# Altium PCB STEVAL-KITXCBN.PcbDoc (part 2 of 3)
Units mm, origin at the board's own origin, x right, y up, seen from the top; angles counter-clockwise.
Board outline 110 x 100 mm, 4 copper layers (Top Layer, GND, PWR, Bottom Layer), stack 1.53 mm thick; 227 components, 137 nets, 699 pads, 698 vias.
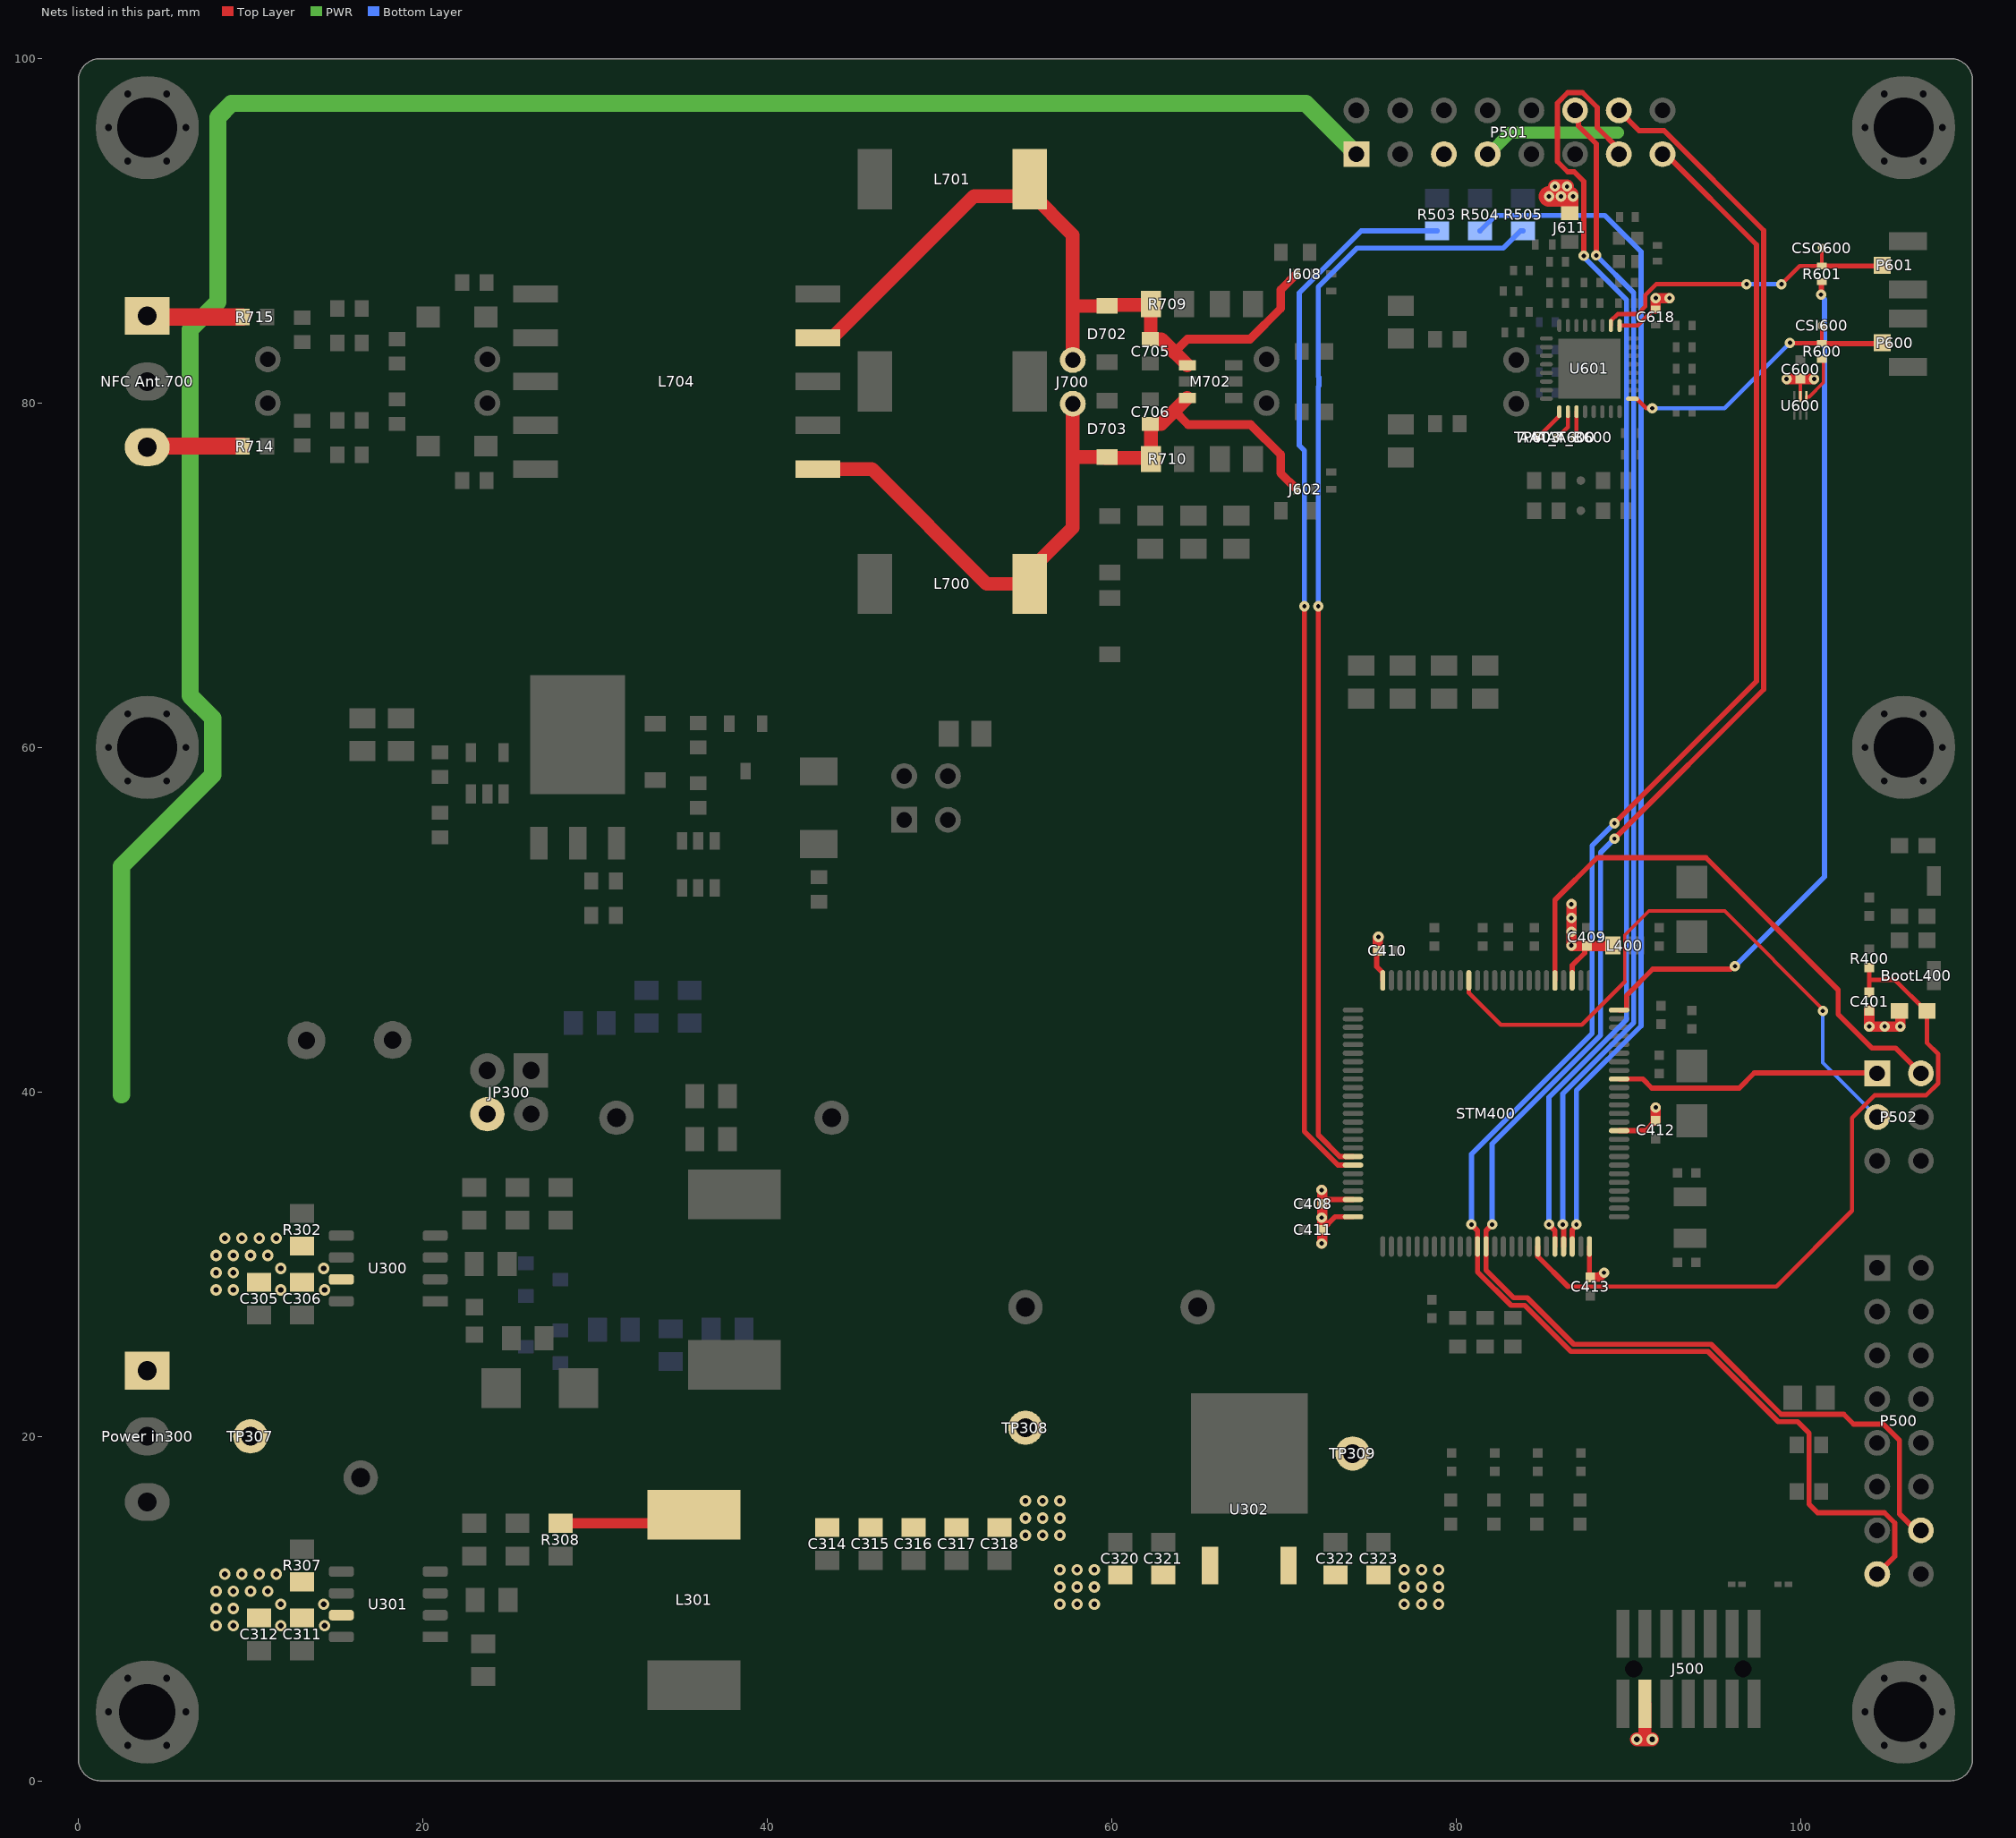
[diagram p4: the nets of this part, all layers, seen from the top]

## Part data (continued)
D700 D704 D705: library part CMP-1060-00492-1, "DIODE ZENER 20V 500MW SOD123", Forward Voltage=900mV, Manufacturer=MCC, Manufacturer Part Number=MMSZ5250B-TP, Max Operating Temperature=150°C, Max Power Dissipation=500mW, Max Reverse Current=100nA, Min Operating Temperature=-55°C, Package Quantity=1, Supplier Part Number 1=MMSZ5250B-TPMSCT-ND, Test Current=6.2mA, Tolerance=5%, Working Voltage=20V
D701: library part CMP-2000-07176-1, "Low Drop Power Schottky Rectifier, 2 A, 25 V, 2-Pin SMD (SMB), RoHS, Tape and Reel", Average Rectified Current=2A, Case/Package=SMB, Forward Voltage=530mV, Manufacturer=STMicroelectronics, Max Forward Surge Current (Ifsm)=75A, Max Operating Temperature=150°C, Max Repetitive Reverse Voltage (Vrrm)=25V, Max Reverse Current=90uA, Min Operating Temperature=-65°C, Package Quantity=1, Supplier Part Number 1=0249404
D702 D703: library part CMP-0895-00001-2, "Switching Diode, 2-Pin SOD-123, Pb-Free, Tape and Reel", Manufacturer="On Semiconductor", Supplier Part Number 1=MMSD4148T1GOSTR-ND
J400 J401 J402: library part solder_jumper_open
J500: "CONNECTOR FTSH-107-01-L-DV-K-A", Manufacturer=SAMTEC, Supplier Part Number 1=FTSH-107-01-L-DV-K-A-ND
J602 J604 J607 J608 J610: library part solder_jumper_open_0402
J603 J609 J611: library part solder_jumper_closed, "0R", Manufacturer=Multicomp, Manufacturer Part Number=MC00625W040210R, Supplier Part Number 1=1357983
J605 J606 J700 J701 J702: library part "Header 2", "Male Single Row Horizontal 2 pin"
JP300: library part JUMPER2V, "2x2 Pin Header", Package=0805, Supplier Part Number 1="2856669 & 2396301"
L300: library part CMP-0227-00732-1, "SMD-Shielded Power Inductor WE-PD, L = 56.0 µH", Case/Size Code=4747, DC Resistance (DCR)=0.11mR, Inductance="56.0 ÂµH", Inductor Application="POWER INDUCTOR", Inductor Type="GENERAL PURPOSE INDUCTOR", Manufacturer="Wurth Electronics", Manufacturer Part Number=744771156, Max Operating Temperature=125°C, Min Operating Temperature=-40°C, Rated Current-Max=2.01A, Self Resonant Frequency=7MHz, Supplier Part Number 1=732-1391-1-ND, Test Frequency=1kHz, Tolerance=20%
L301: library part CMP-0227-00726-1, "SMD-Shielded Power Inductor WE-PD, L = 33.0 µH", Case/Size Code=4747, DC Resistance (DCR)=57mR, Inductance="33.0 ÂµH", Inductor Application="POWER INDUCTOR", Inductor Type="GENERAL PURPOSE INDUCTOR", Manufacturer="Wurth Electronics", Manufacturer Part Number=744771133, Max Operating Temperature=125°C, Min Operating Temperature=-40°C, Package Height=6mm, Package Length=12mm, Package Style=SMTMeter, Rated Current-Max=2.68A, Self Resonant Frequency=10MHz, Supplier Part Number 1=732-1212-1-ND, Test Frequency=1kHz, Tolerance=20%
L400: library part BLM18AG601SN1D, "Ferrite Chip, 1 Function(s), 0.5A, 2 Pin(s)", Case Code=0603, Current Rating=500mA, DC Resistance-Max=380mR, Manufacturer=MURATA, Max Frequency=100MHz, Max Operating Temperature=125°C, Min Operating Temperature=-55°C, Supplier Part Number 1=490-1014-2-ND
L700 L701 L702: library part CMP-1396-00035-1, "SMD-Shielded Power Inductor WE-PD, L=10.0 µH", Inductance="10.0 ÂµH", Manufacturer="Wuerth Elektronik", Supplier Part Number 1=2082675
L703 L705: library part CMP-06042-016297-1, "FIXED IND 470NH 1.4A 70 MOHM SMD", Case Code (Imperial)=1206, Case Code (Metric)=3216, Current Rating=1.4A, DC Resistance (DCR)=87.5mR, Inductance=470nH, Max Operating Temperature=125°C, Min Operating Temperature=-55°C, Package Quantity=3000, Self Resonant Frequency=80MHz, Supplier Part Number 1=490-8429-1-ND, Test Frequency=1MHz, Tolerance=20%
L704: library part 42, Manufacturer=Wurth, Manufacturer PN=750371385
LD401 LD402 LD403 LD404: library part LED2, "LED Uni-Color White 7000K 2-Pin Chip 0603(1608Metric) T/R / LED COOL WHITE 0603 SMD", Case Code (Imperial)=0603, Case Code (Metric)=1608, Color=White, Correlated Color Temperature (CCT)="7000 K", Forward Current=5mA, Forward Voltage=3.15V, Manufacturer="Vishay Semiconductors", Manufacturer Part Number=VLMW1300-GS08, Max Operating Temperature=80°C, Max Power Dissipation=70mW, Min Operating Temperature=-20°C, Package Quantity=3000, Supplier Part Number 1=2251493
M700: library part "P-MOS RSR020P05TL", "Mosfet P-ch 30V 2A S-mini", Case/Package=TO-236-3, Continuous Drain Current (ID)=2A, Drain to Source Voltage (Vdss)=30V, Input Capacitance=159pF, Manufacturer=Toshiba, Max Power Dissipation=600mW, Supplier Part Number 1=SSM3J353FLFCT-ND
M701: "Trans MOSFET N-CH 30V 6A 6-Pin SOT-23 T/R", Case/Package=SOT-23-6, Continuous Drain Current (ID)=6A, Drain to Source Breakdown Voltage=30V, Drain to Source Resistance=40mR, Gate to Source Voltage (Vgs)=20V, Input Capacitance=283pF, Manufacturer=STMicroelectronics, Manufacturer Part Number=STT6N3LLH6, Max Operating Temperature=150°C, Max Power Dissipation=1.6W, Min Operating Temperature=-55°C, Package Quantity=3000, Supplier Part Number 1=07AH7134
M702: library part NDC7002N, "Transistor MOSFET Array Dual N-CH 45V 6-Pin SOT-457T Emboss T/R", Continuous Drain Current (ID)=1A, Drain to Source Voltage (Vdss)=45V, Manufacturer=Rohm, Max Operating Temperature=150°C, Max Power Dissipation=1.25W, Supplier Part Number 1=846-QS6K21FRACT-ND, Threshold Voltage=1.5V
"NFC Ant.700" "Power in300": library part HEADER3, "Screw terminal", Manufacturer="Würth Electronics", Manufacturer Part Number=691214310003, Package=TBD, Supplier Part Number 1=732-691214310003-ND
P500: "Board Connector, 16 Contact(s), 2 Row(s), Female, Straight, 0.1 inch Pitch, Solder Terminal, Black Insulator, Socket", Contact Resistance=10mR, Insulation Color=Black, Manufacturer="Würth Electronics", Manufacturer Part Number=61301621121, Max Operating Temperature=125°C, Min Operating Temperature=-65°C, Supplier Part Number 1=2356136
P501: "Board Connector, 16 Contact(s), 2 Row(s), Male, Straight, 0.1 inch Pitch, Solder Terminal", Manufacturer="Würth Electronics", Manufacturer Part Number=61301621121, Manufacturer Series=HTSW, Supplier Part Number 1=2356136
P502: "Board Connector, 6 Contact(s), 2 Row(s), Male, Straight, 0.1 inch Pitch, Solder Terminal, Black Insulator", Flammability Rating="UL94 V-0", Insulation Color=Black, Manufacturer=Samtec, Manufacturer Part Number=TSW-103-07-F-D, Supplier Part Number 1=SAM10846-ND
P600 P601: Manufacturer="Würth Electronics", Manufacturer Part Number=636101111001, Supplier Part Number 1=3843345
P700: "Header, 2-Pin, Dual row", Supplier Part Number 1=0757571121
Q300 Q301: library part CMP-1048-00779-1, "General Purpose Transistor, NPN Silicon, 3-Pin SOT-23, Pb-Free, Tape and Reel", Manufacturer="On Semiconductor", Supplier Part Number 1=5449393
R300: library part RESISTOR, "Resistor", Package=TBD, Supplier Part Number 1=812-3350, Tolerance=1%
R301 R302 R307: library part RESISTOR, "Resistor", Package=TBD, Supplier Part Number 1=812-3375, Tolerance=1%
R303: library part RESISTOR, "Res Thin Film 0805 150K Ohm 0.1% 1/8W ±25ppm/°C Molded SMD SMD Punched Carrier T/R", Case Code (Imperial)=0805, Case Code (Metric)=2012, Manufacturer=Panasonic, Manufacturer Part Number=ERA-6AEB154V, Max Operating Temperature=155°C, Max Power Dissipation=125mW, Min Operating Temperature=-55°C, Package Quantity=5000, Resistance=150kR, Resistance Tolerance=0.1%, Resistor Type="Thin Film", Supplier Part Number 1=P150KDACT-ND, Temperature Coefficient=25ppm/°C, Voltage Rating=100V
R304: library part RESISTOR, "Res Thick Film 0805 1KOhm 1% 0.125W(1/8W) 100ppm/C Epoxy Pad SMD T/R", Case Code (Imperial)=0805, Case Code (Metric)=2012, Manufacturer=Yageo, Manufacturer Part Number=RC0805FR-071KL, Max Operating Temperature=155°C, Max Power Dissipation=125mW, Min Operating Temperature=-55°C, Package Quantity=1, Resistance=1kR, Resistance Tolerance=1%, Resistor Type="Thick Film", Supplier Part Number 1=311-1.00KCRTR-ND, Temperature Coefficient=100ppm/°C, Voltage Rating=150V
R305: library part RESISTOR, "Res Thick Film 0805 33K Ohm 5% 1/8W ±200ppm/°C Molded SMD Embossed Carrier T/R", Case Code (Imperial)=0805, Case Code (Metric)=2012, Manufacturer=Panasonic, Manufacturer Part Number=ERJ-6GEYJ333V, Max Operating Temperature=155°C, Max Power Dissipation=125mW, Min Operating Temperature=-55°C, Package Quantity=5000, Resistance=33kR, Resistance Tolerance=5%, Resistor Type="Thick Film", Supplier Part Number 1=P33KATR-ND, Temperature Coefficient=200ppm/°C, Voltage Rating=150V
R306: library part RESISTOR, "Res Thick Film 0805 20K Ohm 1% 1/8W +/-100ppm/ßC Molded SMD Punched Carrier T/R", Case Code (Imperial)=0805, Case Code (Metric)=2012, Manufacturer=Panasonic, Manufacturer Part Number=ERJ-6ENF2002V, Max Operating Temperature=155°C, Max Power Dissipation=125mW, Min Operating Temperature=-55°C, Package Quantity=1, Resistance=20kR, Resistance Tolerance=1%, Resistor Type="Thick Film", Supplier Part Number 1=P20.0KCCT-ND, Temperature Coefficient=100ppm/°C, Voltage Rating=150V
R308: library part RESISTOR, "Fixed Resistor, Metal Glaze/thick Film, 0.125W, 402000ohm, 150V, 1% +/-Tol, 100ppm/Cel, Surface Mount, 0805", Manufacturer=Panasonic, Manufacturer Part Number=ERJ-6ENF4023V, Max Operating Temperature=155°C, Min Operating Temperature=-55°C, Package Height=0.6mm, Package Length=2mm, Package Shape=Rectangular, Package Style=SMTMeter, Package Width=1.25mm, Rated Power Dissipation (P)=125mW, Rated Temperature=70°C, Resistor Type="FIXED RESISTOR", Supplier Part Number 1=P402KCCT-ND, Temperature Coefficient=100ppm/°C, Tolerance=1%, Working Voltage=150V
R309: library part RESISTOR, "Fixed Resistor, Thin Film, 0.125W, 82000ohm, 150V, 0.1% +/-Tol, 25ppm/Cel, Surface Mount, 0805", Manufacturer=Yageo, Manufacturer Part Number=RT0805BRD0782KL, Max Operating Temperature=155°C, Min Operating Temperature=-55°C, Package Height=0.5mm, Package Length=2mm, Package Style=SMTMeter, Package Width=1.25mm, Rated Power Dissipation (P)=125mW, Rated Temperature=70°C, Resistor Type="FIXED RESISTOR", Supplier Part Number 1=YAG1981CT-ND, Temperature Coefficient=25ppm/°C, Tolerance=0.1%, Working Voltage=150V
R310: library part RESISTOR, "Res Thick Film 0805 820 Ohm 1% 0.125W ±100ppm/°C Molded SMD Punched Carrier T/R", Case Code (Imperial)=0805, Case Code (Metric)=2012, Manufacturer=Panasonic, Manufacturer Part Number=ERJ-6ENF8200V, Max Operating Temperature=155°C, Max Power Dissipation=125mW, Min Operating Temperature=-55°C, Package Quantity=1, Resistance=820R, Resistance Tolerance=1%, Resistor Type="Thick Film", Supplier Part Number 1=P820CCT-ND, Temperature Coefficient=100ppm/°C, Voltage Rating=150V
R400 R401: library part R_0402, "Fixed Resistor, Metal Glaze/thick Film, 0.1W, 10000ohm, 50V, 1% +/-Tol, 200ppm/Cel, Surface Mount, 0402", Manufacturer=Panasonic, Manufacturer Part Number=ERJ-U02F1002X, Max Operating Temperature=155°C, Min Operating Temperature=-55°C, Package Height=0.35mm, Package Length=1mm, Package Style=SMTMeter, Package Width=0.5mm, Rated Power Dissipation (P)=100mW, Rated Temperature=70°C, Resistor Type="FIXED RESISTOR", Supplier Part Number 1=10-ERJ-U02F1002XCT-ND, Temperature Coefficient=200ppm/°C, Tolerance=1%, Working Voltage=50V
R402 R403 R404 R405 R410: library part R_0402, "Metal Glaze/thick Film, 0.0625W, 0ohm, Surface Mount, 0402", Manufacturer=Yageo, Manufacturer Part Number=RC0402JR-070RL, Max Operating Temperature=155°C, Min Operating Temperature=-55°C, Package Height=0.35mm, Package Length=1mm, Package Shape=Rectangular, Package Style=SMTMeter, Package Width=0.5mm, Rated Power Dissipation (P)=62.5mW, Rated Temperature=70°C, Resistor Type="FIXED RESISTOR", Supplier Part Number 1=311-0.0JRCT-ND
R406 R407 R408 R411: library part R_0402, "VISHAY - CRCW0402120RFKED - RES, THICK FILM, 120R, 1%, 0.063W, 0402, REEL", Case Code (Imperial)=0402, Case Code (Metric)=1005, Manufacturer=Vishay, Manufacturer Part Number=CRCW0402120RFKED, Max Operating Temperature=155°C, Max Power Dissipation=63mW, Min Operating Temperature=-55°C, Package Quantity=10000, Resistor Type="Thick Film", Supplier Part Number 1=541-120LCT-ND, Temperature Coefficient=100ppm/°C, Tolerance=1%, Voltage Rating=50V
R409: library part R_0402, "VISHAY - CRCW040247R0FKED - SMD Chip Resistor, 0402 [1005 Metric], 47 ohm, CRCW e3 Series, 50 V, Thick Film, 63 mW", Case Code (Imperial)=0402, Case Code (Metric)=1005, Manufacturer=Vishay, Manufacturer Part Number=CRCW040247R0FKED, Max Operating Temperature=155°C, Max Power Dissipation=63mW, Min Operating Temperature=-55°C, Package Quantity=10, Resistance Tolerance=1%, Resistor Type="Thick Film", Supplier Part Number 1=541-47.0LCT-ND, Temperature Coefficient=100ppm/°C, Voltage Rating=50V
R500 R502 R712 R716: library part R_0603, "Fixed Resistor, Thin Film, 0.1W, 100ohm, 100V, 0.1% +/-Tol, 25ppm/Cel, Surface Mount, 0603", Manufacturer=Susumu, Manufacturer Part Number=RG1608P-101-B-T5, Max Operating Temperature=155°C, Min Operating Temperature=-55°C, Package Height=0.4mm, Package Length=1.6mm, Package Style=SMTMeter, Package Width=0.8mm, Rated Power Dissipation (P)=166.7mW, Rated Temperature=70°C, Resistor Type="FIXED RESISTOR", Supplier Part Number 1=RG16P100BCT-ND, Temperature Coefficient=25ppm/°C, Tolerance=0.1%, Working Voltage=100V
R501 R504: library part RESISTOR, "Resistor", Package=TBD, Supplier Part Number 1=812-3362, Tolerance=1%
R503 R505: library part RESISTOR, "Metal Glaze/thick Film, 0.0625W, 0ohm, Surface Mount, 0402", Manufacturer=Yageo, Manufacturer Part Number=RC0402JR-070RL, Max Operating Temperature=155°C, Min Operating Temperature=-55°C, Package=TBD, Package Height=0.35mm, Package Length=1mm, Package Shape=Rectangular, Package Style=SMTMeter, Package Width=0.5mm, Rated Power Dissipation (P)=62.5mW, Rated Temperature=70°C, Resistor Type="FIXED RESISTOR", Supplier Part Number 1=812-3362, Tolerance=1%
R600 R601: library part R0402_50R, "50R, 0402", Manufacturer=MULTICOMP, Manufacturer Part Number=MCMR04X49R9FTL, Supplier Part Number 1=2073090
R602 R608 R714 R715: library part R_0603, "Res Thick Film 0603 0 Ohm Molded SMD Automotive Paper T/R", Case Code (Imperial)=0603, Case Code (Metric)=1608, Manufacturer="Vishay Dale", Manufacturer Part Number=CRCW06030000Z0EAHP, Max Operating Temperature=155°C, Max Power Dissipation=250mW, Min Operating Temperature=-55°C, Package Quantity=5000, Resistance=0mR, Supplier Part Number 1=541-0.0SBCT-ND, Temperature Coefficient=0ppm/°C, Voltage Rating=75V
R603 R604 R605 R606 R607 R609: library part R0402_0R, "0R, 0402", Manufacturer=MULTICOMP, Manufacturer Part Number=MC00625W040210R, Supplier Part Number 1=1357983
R610 R611 R705 R707: library part R_0805, "Fixed Resistor, Metal Glaze/thick Film, 0.125W, 10000ohm, 150V, 1% +/-Tol, 100ppm/Cel, Surface Mount, 0805", Manufacturer=Yageo, Manufacturer Part Number=RC0805FR-0710KL, Max Operating Temperature=155°C, Min Operating Temperature=-55°C, Package Height=0.5mm, Package Length=2mm, Package Shape=Rectangular, Package Style=SMTMeter, Package Width=1.25mm, Rated Power Dissipation (P)=125mW, Rated Temperature=70°C, Resistor Type="FIXED RESISTOR", Supplier Part Number 1=311-10.0KCRCT-ND, Temperature Coefficient=100ppm/°C, Tolerance=1%, Working Voltage=150V
R700: library part R_0603, "Fixed Resistor, Thin Film, 0.1W, 10000ohm, 75V, 1% +/-Tol, 50ppm/Cel, Surface Mount, 0603", Manufacturer=Yageo, Manufacturer Part Number=RT0603FRE0710KL, Max Operating Temperature=155°C, Min Operating Temperature=-55°C, Package Height=0.45mm, Package Length=1.6mm, Package Style=SMTMeter, Package Width=0.8mm, Rated Power Dissipation (P)=100mW, Rated Temperature=70°C, Resistance=10kR, Resistor Type="FIXED RESISTOR", Supplier Part Number 1=YAG2321CT-ND, Temperature Coefficient=50ppm/°C, Tolerance=1%, Working Voltage=75V
R701: library part R_0603, "Fixed Resistor, Thin Film, 0.0625W, 2000ohm, 75V, 0.5% +/-Tol, 25ppm/Cel, Surface Mount, 0603", Manufacturer=Susumu, Manufacturer Part Number=RR0816P-202-D, Max Operating Temperature=125°C, Min Operating Temperature=-55°C, Package Height=0.4mm, Package Length=1.6mm, Package Shape=Rectangular, Package Style=SMTMeter, Package Width=0.8mm, Rated Power Dissipation (P)=62.5mW, Resistance=2kR, Resistor Type="FIXED RESISTOR", Supplier Part Number 1=RR08P2.0KDCT-ND, Temperature Coefficient=25ppm/°C, Tolerance=0.5%, Working Voltage=75V
R702: library part R_0603, "Fixed Resistor, Metal Glaze/thick Film, 0.1W, 4220ohm, 75V, 1% +/-Tol, 100ppm/Cel, Surface Mount, 0603", Manufacturer=Vishay, Manufacturer Part Number=CRCW06034K22FKEA, Max Operating Temperature=155°C, Min Operating Temperature=-55°C, Package Height=0.45mm, Package Length=1.55mm, Package Shape=Rectangular, Package Style=SMTMeter, Package Width=0.85mm, Rated Power Dissipation (P)=100mW, Rated Temperature=70°C, Resistance=4.22kR, Resistor Type="FIXED RESISTOR", Supplier Part Number 1=6790465, Temperature Coefficient=100ppm/°C, Tolerance=1%, Working Voltage=75V
R703: library part R_0805, "Fixed Resistor, Metal Glaze/thick Film, 0.125W, 330000ohm, 150V, 1% +/-Tol, 100ppm/Cel, Surface Mount, 0805", Manufacturer=Panasonic, Manufacturer Part Number=ERJ6ENF3303V, Max Operating Temperature=155°C, Min Operating Temperature=-55°C, Package Height=0.6mm, Package Length=2mm, Package Shape=Rectangular, Package Style=SMTMeter, Package Width=1.25mm, Rated Power Dissipation (P)=125mW, Rated Temperature=70°C, Resistor Type="FIXED RESISTOR", Supplier Part Number 1=2303818, Temperature Coefficient=100ppm/°C, Tolerance=1%, Working Voltage=150V
R704: library part R_0603, "Fixed Resistor, Metal Glaze/thick Film, 0.1W, 2ohm, 75V, 5% +/-Tol, 200ppm/Cel, Surface Mount, 0603", Manufacturer="Vishay Dale", Manufacturer Part Number=CRCW06032R00JNEA, Max Operating Temperature=155°C, Min Operating Temperature=-55°C, Package Height=0.45mm, Package Length=1.55mm, Package Shape=Rectangular, Package Style=SMTMeter, Package Width=0.85mm, Rated Power Dissipation (P)=100mW, Rated Temperature=70°C, Resistor Type="FIXED RESISTOR", Supplier Part Number 1=541-2.0GCT-ND, Temperature Coefficient=200ppm/°C, Tolerance=5%, Working Voltage=75V
R706: library part R_0603, "Res General Purpose Thick Film 0603 40.2K Ohm 1% 1/10W ±100ppm/°C Molded SMD Paper T/R", Manufacturer=Yageo, Manufacturer Part Number=RC0603FR-0740K2L, Max Operating Temperature=155°C, Min Operating Temperature=-55°C, Package Height=0.45mm, Package Length=1.6mm, Package Shape=Rectangular, Package Style=SMTMeter, Package Width=0.8mm, Rated Power Dissipation (P)=100mW, Rated Temperature=70°C, Resistance=40.2kR, Resistor Type="FIXED RESISTOR", Supplier Part Number 1=311-40.2KHRCT-ND, Temperature Coefficient=100ppm/°C, Tolerance=1%, Working Voltage=75V
R708: library part R_0805
R709 R710: library part R_0805, "Fixed Resistor, Thin Film, 0.1W, 10ohm, 100V, 0.1% +/-Tol, 10ppm/Cel, Surface Mount, 0805", Manufacturer="TE Connectivity Holsworthy", Manufacturer Part Number=RN73C2A10RBTG, Manufacturer Series=RN73, Max Operating Temperature=125°C, Min Operating Temperature=-55°C, Package Shape=Rectangular, Rated Power Dissipation (P)=100mW, Rated Temperature=70°C, Resistor Type="FIXED RESISTOR", Supplier Part Number 1=A105857-ND, Temperature Coefficient=10ppm/°C, Tolerance=0.1%, Working Voltage=100V
R711: library part R_0603, "Res Thick Film 0603 47K Ohm 1% 1/10W ±100ppm/°C Molded SMD SMD Paper T/R", Case Code (Imperial)=0603, Case Code (Metric)=1608, Manufacturer=Yageo, Manufacturer Part Number=AC0603FR-0747KL, Max Operating Temperature=155°C, Max Power Dissipation=100mW, Min Operating Temperature=-55°C, Resistor Type="Thick Film", Supplier Part Number 1=YAG3610CT-ND, Temperature Coefficient=100ppm/°C, Tolerance=1%, Voltage Rating=50V
R713 R717: library part R_0603, "Res Thick Film 0603 1M Ohm 1% 1/10W ±100ppm/°C Molded SMD Paper T/R", Case Code (Imperial)=0603, Case Code (Metric)=1608, Manufacturer=Yageo, Manufacturer Part Number=AC0603FR-071ML, Max Operating Temperature=155°C, Max Power Dissipation=100mW, Min Operating Temperature=-55°C, Package Quantity=1, Resistance=1MR, Resistor Type="Thick Film", Supplier Part Number 1=311-1MLDCT-ND, Temperature Coefficient=100ppm/°C, Tolerance=1%, Voltage Rating=50V
STM400: "RISC Microcontroller, 32-Bit, FLASH, CORTEX-M4 CPU, 80MHz, CMOS, PQFP100", Manufacturer=STMicroelectronics, Supplier Part Number 1=497-15873-ND
T700: "TRANS NPN 60V 3A DPAK", Case/Package=TO-252, Collector Base Voltage (VCBO)=80V, Collector Emitter Breakdown Voltage=60V, Emitter Base Voltage (VEBO)=6V, Frequency=150MHz, Manufacturer=STMicroelectronics, Manufacturer Part Number=STD1802T4, Max Collector Current=3A, Max Operating Temperature=150°C, Max Power Dissipation=15W, Min Operating Temperature=-65°C, Supplier Part Number 1=497-15633-1-ND
TP300 TP301 TP302 TP303: library part TESTP, "Test Point", Supplier Part Number 1=8731128
TP306 TP307 TP308 TP309: library part TESTP, "Test Point", Supplier Part Number 1=2668701
U300 U301: library part "Voltage Regulator L6981", "Switching Regulator", Manufacturer=STMicroelectronics, Supplier Part Number 1=497-L6981NDRDKR-ND
U302: library part "Voltage Regulator LDF33DT-TR", "LFXX Series 500 mA 3.3 V Fixed VLDO Voltage Regulator with Inhibit - TO-252", Input Bias Current=500uA, Manufacturer=STMicroelctronics, Manufacturer 1=STMicroelectronics, Manufacturer Part Number=LF33CDT-TR, Min Output Voltage=3.3V, Output Voltage Accuracy=2%, Supplier Part Number 1=2112623
U600: "74LVC1G3157 - 2-channel analog multiplexer/demultiplexer", High Level Output Current=50mA, Manufacturer="NXP Semiconductors", Manufacturer Part Number=74LVC1G3157GS,132, Max Operating Temperature=125°C, Max Power Dissipation=250mW, Max Supply Voltage=5.5V, Min Operating Temperature=-40°C, Min Supply Voltage=1.65V, On-State Resistance=15R, Operating Supply Current=40uA, Package Quantity=5000, Supplier Part Number 1=74LVC1G3157GS,132-ND
U601: "NFC Initiator / HF Reader IC", Manufacturer=STMicroelectronics, Manufacturer Part Number=ST25R3916-AQFMCT-ND
U700: library part CMP-0018-00445-1, "Wideband Operational Amplifier, 2.7 to 5 V, -40 to 85 degC, 5-pin SOT23 (DBV5), Green (RoHS & no Sb/Br)", Manufacturer="Texas Instruments", Supplier Part Number 1=THS4304DBVTG4-ND
X400: library part 32_768kHz_Crystal, "FOX ELECTRONICS         FX135A-327            CRYSTAL, 32.768KHZ, 9PF, 3.2 X 1.5MM", Case/Package=SMD/SMT, ESR (Equivalent Series Resistance)=70kR, Frequency=32.768kHz, Frequency Stability=-0.045ppm, Frequency Tolerance=20ppm, Load Capacitance=12.5pF, Manufacturer="Fox Electronics", Manufacturer Part Number=FX135A-327, Max Operating Temperature=85°C, Min Operating Temperature=-40°C, Operating Frequency="32.768 MHz", Package Quantity=3000, Supplier Part Number 1=2064037
Y600: library part "NDK NX2016SA", "Crystal 27.12MHZ 6PF SMD", Manufacturer=NDK, Manufacturer Part Number=NX2016SA-27.12MHZ-EXS00A-CS11337, Supplier Part Number 1=644-1325-1-ND

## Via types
v1: diameter 0.6, hole 0.25, Top Layer to Bottom Layer, 566 vias
v2: diameter 0.66, hole 0.33, Top Layer to Bottom Layer, 94 vias
v3: diameter 0.6, hole 0.25, Top Layer to Bottom Layer, tented both sides, 38 vias

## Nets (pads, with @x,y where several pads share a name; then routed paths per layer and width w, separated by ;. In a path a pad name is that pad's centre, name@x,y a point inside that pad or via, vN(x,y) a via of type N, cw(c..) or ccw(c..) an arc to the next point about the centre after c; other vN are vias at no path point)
3V3: BootL400.2 C322.1 C323.2 C401.1 C408.2 C409.2 C410.2 C411.2 C412.2 C413.2 C600.2 C618.1 J500.3 L400.2 P501.7 STM400.11 STM400.28 STM400.50 STM400.73 STM400.75 STM400.100 TP309.1 U302.3 U600.5 U601.1 | length 44.5
  Top Layer w0.2: U600.5@100,80.2 C600.2@100,81.432
  Top Layer w0.25: U601.1@89.5,84.5 90.563,84.5 91.521,85.457 C618.1@91.6,85.457
  Top Layer w0.3: C411.2@72.233,32 72.983,32.75 STM400.75@74.025,32.75 ; C408.2@72.233,33.5 72.483,33.75 STM400.73@74.025,33.75 ; C410.2@75.467,48.2 75.4,48.133 75.4,47.275 75.75,46.925 STM400.50@75.75,46.475 ; STM400.28@86.75,46.475 86.75,47.35 87.471,48.071 87.471,48.337 C409.2@87.6,48.467 ; STM400.100@87.75,31.025 87.75,29.283 C413.2@87.8,29.233 ; STM400.11@89.475,37.75 91.017,37.75 C412.2@91.6,38.333
  Top Layer w0.55: C413.2@87.8,29.233 88.333,29.233 v1(88.6,29.5)
  Top Layer w0.6: v1(72.2,31.2) 72.233,31.233 C411.2@72.233,32 72.233,32.7 C408.2@72.233,33.5 72.233,33.75 72.233,34.267 v1(72.2,34.3) ; C410.2@75.467,48.2 75.467,48.967 v1(75.5,49) ; v1(86.7,50.9) v1(86.7,50.1) v1(86.7,49.3) v1(86.7,48.5) 86.733,48.467 C409.2@87.6,48.467 89.081,48.467 L400.2@89.114,48.5 ; C412.2@91.6,38.333 v1(91.6,39.1) ; C618.1@91.6,85.457 v1(91.6,86.1) v1(92.4,86.1) ; v1(99.2,81.4) 99.968,81.4 C600.2@100,81.432 100.032,81.4 v1(100.8,81.4) ; C401.1@104,44.717 v1(104,43.8) v1(104.9,43.8) v1(105.8,43.8) 105.8,44.65 BootL400.2@105.75,44.7
  Top Layer w0.7: 90.95,2.4 90.96,2.41
  Top Layer w0.75: 90.96,2.41 J500.3@90.96,4.465
  Top Layer w0.8: v2(90.5,2.4) 90.95,2.4 v2(91.4,2.4)
  PWR w0.7: P501.7@81.84,94.551 P501.7@81.84,94.455 81.896,94.455 83.141,95.7 89.4,95.7
  other v1: 72.2,32.7
  other v2: 77,10.25 78,10.25 79,10.25 77,11.25 78,11.25 79,11.25 77,12.25 78,12.25 79,12.25
5V: C314.2 C315.2 C316.2 C317.2 C318.2 C320.2 C321.1 J611.2 L301.2 P501.5 R308.2 TP308.1 U302.1 | length 11.7
  Top Layer w0.6: R308.2@28,14.95 35.25,14.95 L301.2@35.75,15.45 ; v1@85.75,92.35 v1(85.75,92.575) ; v1@86.2,92 v1(86.8,92) ; J611.2@86.6,91.032 J611.2@86.6,91.275
  Top Layer w0.8: v1(85.75,92.575) v1(86.45,92.575) ; J611.2@86.7,91.132 v1@86.7,92.132
  Top Layer w1.2: v1(85.4,92) 85.75,92 86.2,92 86.4,92
  other v1: 86.1,92
  other v2: 57,10.25 58,10.25 59,10.25 57,11.25 58,11.25 59,11.25 57,12.25 58,12.25 59,12.25 55,14.25 56,14.25 57,14.25 55,15.25 56,15.25 57,15.25 55,16.25 56,16.25 57,16.25
24V: "Power in300.1" C305.2 C306.2 C311.1 C312.2 JP300.4 P501.1 R302.2 R307.2 TP307.1 U300.7 U301.7 | length 127.8
  PWR w1: 2.5,39.836 2.5,53.1 7.8,58.4 7.8,61.7 6.5,63 6.5,84.278 8.1,85.878 8.1,96.6 8.9,97.4 71.275,97.4 P501.1@74.22,94.455
  other v2: 8,9 9,9 11.75,9 14.3,9 8,10 9,10 11.75,10.25 14.25,10.25 8,11 9,11 10,11 11,11 8.5,12 9.5,12 10.5,12 11.5,12 8,28.5 9,28.5 11.75,28.5 14.3,28.5 8,29.5 9,29.5 11.75,29.75 14.25,29.75 8,30.5 9,30.5 10,30.5 11,30.5 8.5,31.5 9.5,31.5 10.5,31.5 11.5,31.5
AAT_A: AAT_A600.1 U601.18 | length 1.7
  Top Layer w0.25: AAT_A600.1@85.9,78 86.5,78.6 U601.18@86.5,79.5
AAT_B: AAT_B600.1 U601.19 | length 1.5
  Top Layer w0.25: AAT_B600.1@86.9,78 86.9,78.068 87,78.168 U601.19@87,79.5
Ant1: "NFC Ant.700.1" R715.2 | length 5.6
  Top Layer w1: 4,85.06 4.06,85 R715.2@9.539,85
Ant2: "NFC Ant.700.3" R714.2 | length 5.6
  Top Layer w1: 4,77.44 4.06,77.5 R714.2@9.539,77.5
BOOT0: BootL400.1 C401.2 R400.2 STM400.94 | length 42.6
  Top Layer w0.25: 86.5,28.7 98.6,28.7 103,33.1 103,38.494 104.316,39.81 107.31,39.81 108,40.5 108,42.195 107.35,42.845 BootL400.1@107.35,44.7 107.3,44.7 105.5,46.5 104,46.5 ; C401.2@104,45.783 104,46.5 ; R400.2@104,47.217 104,46.5
  Top Layer w0.3: STM400.94@84.75,31.025 84.75,30.45 86.5,28.7
COM_Slot: P500.14 P501.14 STM400.88 | length 112.4
  Top Layer w0.3: v1(82.1,32.3) 81.75,31.95 STM400.88@81.75,31.025 81.75,29.648 83.346,28.052 84.143,28.052 86.845,25.35 94.811,25.35 98.886,21.275 102.525,21.275 103.09,20.71 104.82,20.71 105.75,19.78 105.75,15.5 106.71,14.54 P500.14@107,14.54 ; v1(89.2,54.7) 97.875,63.375 97.875,90.03 92.082,95.822 90.633,95.822 P501.14@89.46,96.995
  Bottom Layer w0.3: v1(82.1,32.3) 82.1,36.99 88.4,43.29 88.4,53.9 v1(89.2,54.7)
CSI: R600.1 U600.4 | length 2.9
  Top Layer w0.2: U600.4@100.35,80.2 100.35,80.365 100.515,80.365 101.338,81.188 101.338,82.454 R600.1@101.25,82.543
CSI_out: CSI600.1 P600.1 R600.2 U601.25 | length 17.4
  Top Layer w0.2: R600.2@101.25,83.457 CSI600.1@101.25,84.5
  Top Layer w0.25: U601.25@90.25,80.25 90.5,80.25 91.05,79.7 v1(91.4,79.7) ; v1(99.4,83.5) 99.421,83.479 101.229,83.479 R600.2@101.25,83.457
  Top Layer w0.3: R600.2@101.25,83.457 104.707,83.457 P600.1@104.75,83.5
  Bottom Layer w0.25: v1(91.4,79.7) 95.6,79.7 v1(99.4,83.5)
CSO: R601.1 STM400.25 | length 50.3
  Top Layer w0.3: STM400.25@89.475,44.75 89.9,44.75 89.9,45.6 91.425,47.125 95.944,47.125 96.119,47.3 v1(96.2,47.3) ; v1(101.2,86.3) 101.225,86.325 101.225,87.018 R601.1@101.25,87.043
  Bottom Layer w0.3: v1(96.2,47.3) 101.4,52.5 101.4,86.019 101.2,86.219 v1(101.2,86.3)
CSO_out: CSO600.1 P601.1 R601.2 U601.2 | length 18.8
  Top Layer w0.2: R601.2@101.25,87.957 CSO600.1@101.25,89
  Top Layer w0.25: U601.2@89,84.5 89,84.78 89.381,85.161 90.551,85.161 91,85.61 91,86.278 91.622,86.9 v1(96.875,86.9) ; v1(98.9,86.9) 99.957,87.957 R601.2@101.25,87.957
  Top Layer w0.3: R601.2@101.25,87.957 104.707,87.957 P601.1@104.75,88
  Bottom Layer w0.25: v1(96.875,86.9) v1(98.9,86.9)
DAC1_OUT2: P502.2 STM400.30 | length 33
  Top Layer w0.3: STM400.30@85.75,46.475 85.75,51.15 88.2,53.6 94.518,53.6 102.2,45.918 102.2,44.5 104.157,42.543 105.537,42.543 P502.2@107,41.08
DR1: C705.1 D702.2 J608.1 J700.2 L701.1 L704.4 M702.4 R709.1 | length 46.9
  Top Layer w0.5: C705.1@62.25,83.711 C705.1@62.267,83.711 ; 63.648,82.952 64.406,83.711 68.04,83.711 69.821,85.492 69.821,86.571 J608.1@70.75,87.5
  Top Layer w0.8: L704.4@42.95,83.79 43.05,83.89 43.89,83.89 52.019,92.019 54.65,92.019 55.25,92.619 L701.1@55.25,93 55.25,92.25 57.751,89.749 57.751,85.626 ; J700.2@57.75,82.5 J700.2@57.75,82.5 57.751,85.626 ; D702.2@59.65,85.69 62.238,85.69 62.274,85.726 62.274,83.718 C705.1@62.267,83.711 ; D702.2@59.75,85.635 57.76,85.635 57.751,85.626 ; C705.1@62.25,83.711 62.256,83.705 62.895,83.705 63.648,82.952 M702.4@64.4,82.2
DR2: C706.2 D703.2 J602.1 J700.1 L700.1 L704.1 M702.6 R710.1 | length 45.7
  Top Layer w0.5: 63.648,79.548 64.445,78.75 68.079,78.75 69.821,77.008 69.821,75.929 J602.1@70.75,75
  Top Layer w0.8: L704.1@42.95,76.17 46.08,76.17 52.75,69.5 L700.1@55.25,69.5 55.85,70.1 55.85,70.875 57.732,72.757 57.732,76.865 ; J700.1@57.75,79.96 57.732,79.942 57.732,76.865 ; D703.2@59.65,76.81 62.238,76.81 R710.1@62.298,76.75 62.298,78.782 62.291,78.789 C706.2@62.25,78.789 62.256,78.795 62.895,78.795 63.648,79.548 M702.6@64.4,80.3 ; D703.2@59.75,76.865 57.732,76.865
Ext_LM: TP603.1 U601.17 | length 2
  Top Layer w0.25: TP603.1@84.75,78 86,79.25 U601.17@86,79.5
FOD_ADC3_IN3: P502.1 STM400.17 | length 15.6
  Top Layer w0.3: STM400.17@89.475,40.75 90.85,40.75 91.375,40.225 96.447,40.225 97.322,41.1 P502.1@104.46,41.1
FOD_PWM: P502.3 STM400.40 | length 36.3
  Top Layer w0.2: 89.8,46.4 89.8,49.098 91.202,50.5 95.6,50.5 101.3,44.8 v1(101.3,44.7)
  Top Layer w0.25: STM400.40@80.75,46.475 80.75,45.75 82.6,43.9 87.3,43.9 89.8,46.4
  Bottom Layer w0.2: v1(101.3,44.7) 101.3,41.7 P502.3@104.46,38.54
FOD_Ready: P501.13 STM400.96 | length 76.4
  Top Layer w0.3: v1(85.4,32.3) 85.75,31.95 STM400.96@85.75,31.025 ; v1(87.425,88.55) 87.425,92.875 86.87,93.43 86.495,93.43 85.895,94.03 85.895,97.42 86.495,98.02 87.345,98.02 88.2,97.165 88.2,96 89.46,94.74 P501.13@89.46,94.455
  Bottom Layer w0.3: v1(85.4,32.3) 85.4,39.689 89.9,44.189 89.9,86 87.425,88.475 v1(87.425,88.55)
FOD_Reset: R504.2 STM400.98 | length 70
  Top Layer w0.3: STM400.98@86.75,31.025 86.75,31.986 87,32.236 v1(87,32.3)
  Bottom Layer w0.3: R504.2@81.4,90 82.3,90.9 88.639,90.9 90.75,88.789 90.75,43.836 87,40.086 v1(87,32.3)
FOD_Slot: P500.15 P501.15 STM400.87 | length 110.4
  Top Layer w0.3: v1(80.9,32.3) 81.25,31.95 STM400.87@81.25,31.025 81.25,29.547 83.197,27.6 83.994,27.6 86.669,24.925 94.635,24.925 98.71,20.85 99.839,20.85 100.5,20.189 100.5,16.061 100.996,15.565 104.885,15.565 105.485,14.965 105.485,13.025 P500.15@104.46,12 ; v1(89.2,55.6) 97.45,63.85 97.45,89.192 92.187,94.455 P501.15@92,94.455
  Bottom Layer w0.3: v1(80.9,32.3) 80.9,36.391 87.9,43.391 87.9,54.3 v1(89.2,55.6)
FOD_Uart_Rx: R503.1 STM400.69 | length 61.9
  Top Layer w0.3: v1(71.2,68.2) 71.2,37.699 73.149,35.75 STM400.69@74.025,35.75
  Bottom Layer w0.3: v1(71.2,68.2) 71.2,77.241 70.9,77.541 70.9,86.4 74.5,90 R503.1@78.9,90
FOD_Uart_Tx: R505.1 STM400.68 | length 65.1
  Top Layer w0.3: v1(72,68.2) 72,37.5 73.25,36.25 STM400.68@74.025,36.25
  Bottom Layer w0.3: v1@72,68.226 72,80.962 72.05,81.012 72.05,81.488 72,81.538 72,86.75 74.25,89 82.75,89 83.75,90 R505.1@83.9,90
FOD_Wake_Up: P501.12 STM400.97 | length 69.1
  Top Layer w0.3: v1(86.204,32.303) 86.25,32.257 STM400.97@86.25,31.025 ; P501.12@86.92,96.995 87.111,96.804 87.111,96.089 88.15,95.05 v1(88.15,88.575)
  Bottom Layer w0.3: v1(86.204,32.303) 86.204,39.891 90.325,44.012 90.325,86.4 v1(88.15,88.575)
